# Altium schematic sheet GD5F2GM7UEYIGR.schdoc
size 127 x 101 mm
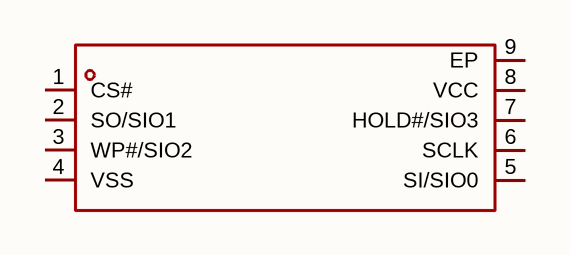
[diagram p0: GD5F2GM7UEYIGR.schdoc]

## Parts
U?  gd5f2gm7ueyigr  [WSON-8_L8.0-W6.0-P1.27-TL-1]  (value not drawn)

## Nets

Not connected (* = marked no-connect by the designer): U? 1(CS#) 2(SO/SIO1) 3(WP#/SIO2) 4(VSS) 5(SI/SIO0) 6(SCLK) 7(HOLD#/SIO3) 8(VCC) 9(EP)

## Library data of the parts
U? = gd5f2gm7ueyigr: 存储容量:2Gbit;时钟频率(fc):133MHz;工作电压:2.7V~3.6V;; Manufacturer: GigaDevice(兆易创新); AddInBom: yes; ModelId: f7358afd81b248ccb497b4df88085798; ModelTransform: 315.7474,236.22,0,0,0,0,0,0,0; Memory Size: 2Gbit; Interface: SPI; Clock Frequency: 133MHz; Page Program time (TPP): 320us; Block Erase Time(tBE): 3ms; Data Retention - TDR (Year): 10年; Standby Supply Current: 50uA; Program / Erase Cycles: 8万次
